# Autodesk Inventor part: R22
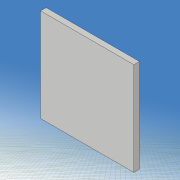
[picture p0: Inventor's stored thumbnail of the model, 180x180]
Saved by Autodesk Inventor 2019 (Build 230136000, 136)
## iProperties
Created: 2021-05
Part Number: R22
Material: 一般
Document SubType Name: Modeling
Designer: kikut
Density: 1 g/cm^3
Appearance: 既定
Mass: 0.06 g
Surface Area: 2.24 cm^2
Volume: 0.06 cm^3
Author: kikut
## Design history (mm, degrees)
sketch "スケッチ1"
  geometry: L1 (80, 60)-(-80, 60); L2 (-80, 60)-(-80, -60); L3 (-80, -60)-(80, -60); L4 (80, -60)-(80, 60); L5 (80, 60)-(-80, -60); L6 (-80, 60)-(80, -60); 1 further point
  constraints: 12 end point, 2 midpoint, 2 parallel, 1 horizontal, 1 perpendicular
  dimensions: "d0" = 160 distance of L2.end L3.end; "d1" = 120 distance of L1.end L2.end
extrude "押し出し1" new body sketch "スケッチ1" stored distance "d2" = 0.6; taper "d3" = 0 deg
sketch "スケッチ2"
  geometry: L1 (-140, 0)-(140, 0) reference; L2 (0, -54)-(20, -30); L3 (0, 54)-(20, 30); L4 (0, -3)-(6.514, -3); L5 (6.514, -3)-(16, -6); L6 (16, -6)-(24, -3); L7 (24, -3)-(33.716, -3); L8 (0, 3)-(6.514, 3); L9 (6.514, 3)-(16, 6); L10 (16, 6)-(24, 3); L11 (24, 3)-(33.716, 3); L12 (0, -98)-(0, 98) reference; L13 (-100, -70)-(100, -70); L14 (100, -70)-(100, 70); L15 (100, 70)-(-100, 70); L16 (-100, 70)-(-100, -70); L17 (-100, -70)-(100, 70); L18 (100, -70)-(-100, 70); A1 r 60 centre (54.312, 28.5) between (0, 54) and (0, 3); A2 r 60 centre (54.312, -28.5) between (0, -3) and (0, -54); A3 r 18.111 centre (18, -12) between (20, -30) and (33.716, -3); A4 r 18.111 centre (18, 12) between (33.716, 3) and (20, 30); 1 further point
  constraints: 32 end point, 8 point on circle, 8 symmetric about line, 4 centre point, 3 horizontal, 2 collinear, 2 midpoint, 2 parallel, 1 perpendicular
  dimensions: "d5" = 60 radius of A1; "d6" = 6 distance of L8.start L4.start; "d7" = 108 distance of L3.start L2.start; "d8" = 0 horizontal distance of L3.start L8.start; "d9" = 60 distance of L3.end L2.end; "d10" = 0 horizontal distance of point (0, 0) L3.start; "d11" = 20 horizontal distance of L3.start L3.end; "d12" = 24 distance of A4.centre A3.centre; "d13" = 6 distance of L11.end L7.end; "d14" = 12 distance of L9.end L5.end; "d15" = 16 distance from line of L12 L5.end; "d16" = 24 distance from line of L6.end L12; "d17" = 200 distance of L14.end L15.end; "d18" = 140 distance of L15.end L13.start; "d30" = 18 distance from line of L12 A4.centre
extrude "押し出し2" cut sketch "スケッチ2" stored distance "d19" = 10; taper "d20" = 0 deg
sketch "スケッチ3"
  geometry: L1 (49.705, -17.97)-(33.948, -15.191); L2 (33.948, -15.191)-(34.295, -13.222); L3 (34.295, -13.222)-(50.052, -16); L4 (50.052, -16)-(49.705, -17.97); L5 (49.705, -17.97)-(34.295, -13.222); L6 (33.948, -15.191)-(50.052, -16); L7 (50.052, 16)-(34.295, 13.222); L8 (34.295, 13.222)-(33.948, 15.191); L9 (33.948, 15.191)-(49.705, 17.97); L10 (49.705, 17.97)-(50.052, 16); L11 (50.052, 16)-(33.948, 15.191); L12 (34.295, 13.222)-(49.705, 17.97); L13 (-112, 0)-(112, 0) reference; L14 (0, -84)-(0, 84) reference; 3 further points
  constraints: 24 end point, 4 midpoint, 4 parallel, 2 perpendicular, 2 symmetric about line
  dimensions: "d21" = 2 distance of L3.end L1.start; "d22" = 2 distance of L9.end L7.start; "d23" = 16 distance of L8.end L9.end; "d24" = 42 distance from line of L14 point (42, 15.596); "d26" = 10 deg angle of L7 L13; "d62" = 16 distance from line of L3.end L13
extrude "押し出し3" join sketch "スケッチ3" distance "d27" = 0.6; taper "d28" = 0 deg
fillet "フィレット1" dims "d31" = 2
fillet "フィレット2" dims "d32" = 1
sketch "スケッチ6"
  geometry: L1 (-20, 60)-(80, 60); L2 (80, 60)-(80, -60); L3 (80, -60)-(-20, -60); L4 (-20, -60)-(-20, 60); L5 (-46.168, 0)-(93.832, 0) reference; L6 (0, -84)-(0, 84) reference; L7 (10, 20)-(20, 20); L8 (20, 20)-(20, 30); L9 (20, 30)-(10, 30); L10 (10, 30)-(10, 20); 1 further point
  constraints: 16 end point, 4 parallel, 2 horizontal, 2 perpendicular, 1 other
  dimensions: "d63" = 120 distance of L3.end L1.start; "d64" = 100 distance of L1.start L1.end; "d65" = 20 distance between parallel lines of L6 L4; "d66" = 10 distance of L8.end L9.end; "d73" = 10 distance of L9.end L7.start; "d74" = 20 distance between parallel lines of L7 L5; "d75" = 30 distance between parallel lines of L10 L4
extrude "押し出し4" cut sketch "スケッチ6" stored distance "d70" = 10; taper "d71" = 0 deg
node "ソリッド1"
